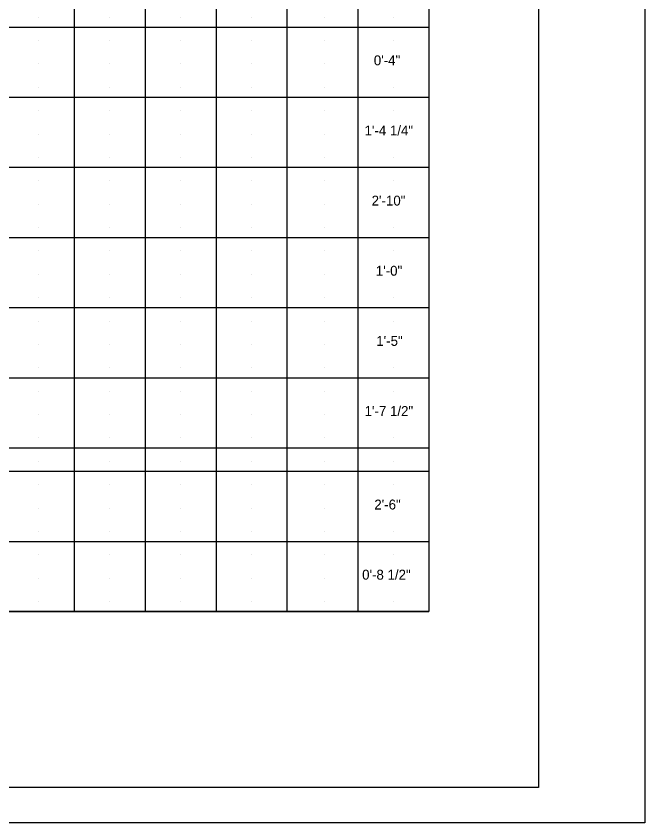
# Model space of a CAD drawing. Extents: x -31.1 to 2.9, y 8.5 to 31.4.
# Drawn here: x -6 to 2.87, y 8.48 to 19.87 of the extents above; entities that cross this region are included whole.
import ezdxf

# ---------------------------------------------------------------- set-up
doc = ezdxf.new("R2010")
doc.units = 0
doc.layers.add('BR_P_Gen_Text', color=7, linetype='Continuous')
doc.layers.add('SC_Scratch1', color=7, linetype='Continuous')

msp = doc.modelspace()

# ---------------------------------------------------------------- linework, layer by layer
at = {"layer": 'BR_P_Gen_Text'}
for p, q in [((-0.178, 29.627), (-0.178, 11.467)), ((-5.178, 28.577), (-5.178, 11.467)), ((-4.178, 28.577), (-4.178, 11.467)), ((-3.178, 28.577), (-3.178, 11.467)), ((-2.178, 28.577), (-2.178, 11.467)), ((-1.178, 28.577), (-1.178, 11.467)), ((-14.678, 19.717), (-0.178, 19.717)), ((-14.678, 18.727), (-0.178, 18.727)), ((-14.678, 17.737), (-0.178, 17.737)), ((-14.678, 16.747), (-0.178, 16.747)), ((-14.678, 15.757), (-0.178, 15.757)), ((-14.678, 14.767), (-0.178, 14.767)), ((-14.678, 13.777), (-0.178, 13.777)), ((-14.678, 13.447), (-0.178, 13.447)), ((-14.678, 12.457), (-0.178, 12.457)), ((-0.178, 11.467), (-14.678, 11.467)), ((-14.678, 11.467), (-0.178, 11.467)), ((-14.678, 11.467), (-0.178, 11.467))]:
    msp.add_line(p, q, dxfattribs=at)
for points in [[(-31.128, 30.484), (2.872, 30.484), (2.872, 8.484), (-31.128, 8.484)], [(-29.128, 29.984), (1.372, 29.984), (1.372, 8.984), (-29.128, 8.984)]]:
    msp.add_lwpolyline(points, close=True, dxfattribs=at)
at = {"layer": 'SC_Scratch1'}
for p, q in [((-5.677, 19.857), (-5.677, 19.857)), ((-5.677, 19.857), (-5.677, 19.857)), ((-4.678, 19.857), (-4.678, 19.857)), ((-4.678, 19.857), (-4.678, 19.857)), ((-3.678, 19.857), (-3.678, 19.857)), ((-2.678, 19.857), (-2.678, 19.857)), ((-1.655, 19.857), (-1.655, 19.857)), ((-0.678, 19.857), (-0.678, 19.857)), ((-5.677, 19.527), (-5.677, 19.527)), ((-5.677, 19.527), (-5.677, 19.527)), ((-4.678, 19.527), (-4.678, 19.527)), ((-4.678, 19.527), (-4.678, 19.527)), ((-3.678, 19.527), (-3.678, 19.527)), ((-2.678, 19.527), (-2.678, 19.527)), ((-1.655, 19.527), (-1.655, 19.527)), ((-0.678, 19.527), (-0.678, 19.527)), ((-5.677, 19.197), (-5.677, 19.197)), ((-5.677, 19.197), (-5.677, 19.197)), ((-4.678, 19.197), (-4.678, 19.197)), ((-4.678, 19.197), (-4.678, 19.197)), ((-3.678, 19.197), (-3.678, 19.197)), ((-2.678, 19.197), (-2.678, 19.197)), ((-1.655, 19.197), (-1.655, 19.197)), ((-0.678, 19.197), (-0.678, 19.197)), ((-5.677, 18.867), (-5.677, 18.867)), ((-5.677, 18.867), (-5.677, 18.867)), ((-4.678, 18.867), (-4.678, 18.867)), ((-4.678, 18.867), (-4.678, 18.867)), ((-3.678, 18.867), (-3.678, 18.867)), ((-2.678, 18.867), (-2.678, 18.867)), ((-1.655, 18.867), (-1.655, 18.867)), ((-0.678, 18.867), (-0.678, 18.867)), ((-5.677, 18.537), (-5.677, 18.537)), ((-5.677, 18.537), (-5.677, 18.537)), ((-4.678, 18.537), (-4.678, 18.537)), ((-4.678, 18.537), (-4.678, 18.537)), ((-3.678, 18.537), (-3.678, 18.537)), ((-2.678, 18.537), (-2.678, 18.537)), ((-1.655, 18.537), (-1.655, 18.537)), ((-0.678, 18.537), (-0.678, 18.537)), ((-5.677, 18.207), (-5.677, 18.207)), ((-5.677, 18.207), (-5.677, 18.207)), ((-4.678, 18.207), (-4.678, 18.207)), ((-4.678, 18.207), (-4.678, 18.207)), ((-3.678, 18.207), (-3.678, 18.207)), ((-2.678, 18.207), (-2.678, 18.207)), ((-1.655, 18.207), (-1.655, 18.207)), ((-0.678, 18.207), (-0.678, 18.207)), ((-5.677, 17.877), (-5.677, 17.877)), ((-5.677, 17.877), (-5.677, 17.877)), ((-4.678, 17.877), (-4.678, 17.877)), ((-4.678, 17.877), (-4.678, 17.877)), ((-3.678, 17.877), (-3.678, 17.877)), ((-2.678, 17.877), (-2.678, 17.877)), ((-1.655, 17.877), (-1.655, 17.877)), ((-0.678, 17.877), (-0.678, 17.877)), ((-5.677, 17.547), (-5.677, 17.547)), ((-5.677, 17.547), (-5.677, 17.547)), ((-4.678, 17.547), (-4.678, 17.547)), ((-4.678, 17.547), (-4.678, 17.547)), ((-3.678, 17.547), (-3.678, 17.547)), ((-2.678, 17.547), (-2.678, 17.547)), ((-1.655, 17.547), (-1.655, 17.547)), ((-0.678, 17.547), (-0.678, 17.547)), ((-5.677, 17.217), (-5.677, 17.217)), ((-5.677, 17.217), (-5.677, 17.217)), ((-4.678, 17.217), (-4.678, 17.217)), ((-4.678, 17.217), (-4.678, 17.217)), ((-3.678, 17.217), (-3.678, 17.217)), ((-2.678, 17.217), (-2.678, 17.217)), ((-1.655, 17.217), (-1.655, 17.217)), ((-0.678, 17.217), (-0.678, 17.217)), ((-5.677, 16.887), (-5.677, 16.887)), ((-5.677, 16.887), (-5.677, 16.887)), ((-4.678, 16.887), (-4.678, 16.887)), ((-4.678, 16.887), (-4.678, 16.887)), ((-3.678, 16.887), (-3.678, 16.887)), ((-2.678, 16.887), (-2.678, 16.887)), ((-1.655, 16.887), (-1.655, 16.887)), ((-0.678, 16.887), (-0.678, 16.887)), ((-5.677, 16.557), (-5.677, 16.557)), ((-5.677, 16.557), (-5.677, 16.557)), ((-4.678, 16.557), (-4.678, 16.557)), ((-4.678, 16.557), (-4.678, 16.557)), ((-3.678, 16.557), (-3.678, 16.557)), ((-2.678, 16.557), (-2.678, 16.557)), ((-1.655, 16.557), (-1.655, 16.557)), ((-0.678, 16.557), (-0.678, 16.557)), ((-5.677, 16.227), (-5.677, 16.227)), ((-5.677, 16.227), (-5.677, 16.227)), ((-4.678, 16.227), (-4.678, 16.227)), ((-4.678, 16.227), (-4.678, 16.227)), ((-3.678, 16.227), (-3.678, 16.227)), ((-2.678, 16.227), (-2.678, 16.227)), ((-1.655, 16.227), (-1.655, 16.227)), ((-0.678, 16.227), (-0.678, 16.227)), ((-5.677, 15.897), (-5.677, 15.897)), ((-5.677, 15.897), (-5.677, 15.897)), ((-4.678, 15.897), (-4.678, 15.897)), ((-4.678, 15.897), (-4.678, 15.897)), ((-3.678, 15.897), (-3.678, 15.897)), ((-2.678, 15.897), (-2.678, 15.897)), ((-1.655, 15.897), (-1.655, 15.897)), ((-0.678, 15.897), (-0.678, 15.897)), ((-5.677, 15.567), (-5.677, 15.567)), ((-5.677, 15.567), (-5.677, 15.567)), ((-4.678, 15.567), (-4.678, 15.567)), ((-4.678, 15.567), (-4.678, 15.567)), ((-3.678, 15.567), (-3.678, 15.567)), ((-2.678, 15.567), (-2.678, 15.567)), ((-1.655, 15.567), (-1.655, 15.567)), ((-0.678, 15.567), (-0.678, 15.567)), ((-5.677, 15.237), (-5.677, 15.237)), ((-5.677, 15.237), (-5.677, 15.237)), ((-4.678, 15.237), (-4.678, 15.237)), ((-4.678, 15.237), (-4.678, 15.237)), ((-3.678, 15.237), (-3.678, 15.237)), ((-2.678, 15.237), (-2.678, 15.237)), ((-1.655, 15.237), (-1.655, 15.237)), ((-0.678, 15.237), (-0.678, 15.237)), ((-5.677, 14.907), (-5.677, 14.907)), ((-5.677, 14.907), (-5.677, 14.907)), ((-4.678, 14.907), (-4.678, 14.907)), ((-4.678, 14.907), (-4.678, 14.907)), ((-3.678, 14.907), (-3.678, 14.907)), ((-2.678, 14.907), (-2.678, 14.907)), ((-1.655, 14.907), (-1.655, 14.907)), ((-0.678, 14.907), (-0.678, 14.907)), ((-5.677, 14.577), (-5.677, 14.577)), ((-5.677, 14.577), (-5.677, 14.577)), ((-4.678, 14.577), (-4.678, 14.577)), ((-4.678, 14.577), (-4.678, 14.577)), ((-3.678, 14.577), (-3.678, 14.577)), ((-2.678, 14.577), (-2.678, 14.577)), ((-1.655, 14.577), (-1.655, 14.577)), ((-0.678, 14.577), (-0.678, 14.577)), ((-5.677, 14.247), (-5.677, 14.247)), ((-5.677, 14.247), (-5.677, 14.247)), ((-4.678, 14.247), (-4.678, 14.247)), ((-4.678, 14.247), (-4.678, 14.247)), ((-3.678, 14.247), (-3.678, 14.247)), ((-2.678, 14.247), (-2.678, 14.247)), ((-1.655, 14.247), (-1.655, 14.247)), ((-0.678, 14.247), (-0.678, 14.247)), ((-5.677, 13.917), (-5.677, 13.917)), ((-5.677, 13.917), (-5.677, 13.917)), ((-4.678, 13.917), (-4.678, 13.917)), ((-4.678, 13.917), (-4.678, 13.917)), ((-3.678, 13.917), (-3.678, 13.917)), ((-2.678, 13.917), (-2.678, 13.917)), ((-1.655, 13.917), (-1.655, 13.917)), ((-0.678, 13.917), (-0.678, 13.917)), ((-5.677, 13.587), (-5.677, 13.587)), ((-5.677, 13.587), (-5.677, 13.587)), ((-4.678, 13.587), (-4.678, 13.587)), ((-4.678, 13.587), (-4.678, 13.587)), ((-3.678, 13.587), (-3.678, 13.587)), ((-2.678, 13.587), (-2.678, 13.587)), ((-1.655, 13.587), (-1.655, 13.587)), ((-0.678, 13.587), (-0.678, 13.587)), ((-5.677, 13.257), (-5.677, 13.257)), ((-5.677, 13.257), (-5.677, 13.257)), ((-4.678, 13.257), (-4.678, 13.257)), ((-4.678, 13.257), (-4.678, 13.257)), ((-3.678, 13.257), (-3.678, 13.257)), ((-2.678, 13.257), (-2.678, 13.257)), ((-1.655, 13.257), (-1.655, 13.257)), ((-0.678, 13.257), (-0.678, 13.257)), ((-5.677, 12.927), (-5.677, 12.927)), ((-5.677, 12.927), (-5.677, 12.927)), ((-4.678, 12.927), (-4.678, 12.927)), ((-4.678, 12.927), (-4.678, 12.927)), ((-3.678, 12.927), (-3.678, 12.927)), ((-2.678, 12.927), (-2.678, 12.927)), ((-1.655, 12.927), (-1.655, 12.927)), ((-0.678, 12.927), (-0.678, 12.927)), ((-5.677, 12.597), (-5.677, 12.597)), ((-5.677, 12.597), (-5.677, 12.597)), ((-4.678, 12.597), (-4.678, 12.597)), ((-4.678, 12.597), (-4.678, 12.597)), ((-3.678, 12.597), (-3.678, 12.597)), ((-2.678, 12.597), (-2.678, 12.597)), ((-1.655, 12.597), (-1.655, 12.597)), ((-0.678, 12.597), (-0.678, 12.597)), ((-5.677, 12.267), (-5.677, 12.267)), ((-5.677, 12.267), (-5.677, 12.267)), ((-4.678, 12.267), (-4.678, 12.267)), ((-4.678, 12.267), (-4.678, 12.267)), ((-3.678, 12.267), (-3.678, 12.267)), ((-2.678, 12.267), (-2.678, 12.267)), ((-1.655, 12.267), (-1.655, 12.267)), ((-0.678, 12.267), (-0.678, 12.267)), ((-5.677, 11.937), (-5.677, 11.937)), ((-5.677, 11.937), (-5.677, 11.937)), ((-4.678, 11.937), (-4.678, 11.937)), ((-4.678, 11.937), (-4.678, 11.937)), ((-3.678, 11.937), (-3.678, 11.937)), ((-2.678, 11.937), (-2.678, 11.937)), ((-1.655, 11.937), (-1.655, 11.937)), ((-0.678, 11.937), (-0.678, 11.937)), ((-5.677, 11.607), (-5.677, 11.607)), ((-5.677, 11.607), (-5.677, 11.607)), ((-4.678, 11.607), (-4.678, 11.607)), ((-4.678, 11.607), (-4.678, 11.607)), ((-3.678, 11.607), (-3.678, 11.607)), ((-2.678, 11.607), (-2.678, 11.607)), ((-1.655, 11.607), (-1.655, 11.607)), ((-0.678, 11.607), (-0.678, 11.607))]:
    msp.add_line(p, q, dxfattribs=at)

# ---------------------------------------------------------------- texts
at = {"layer": 'BR_P_Gen_Text'}
for s, p in [('0\'-4"', (-0.952, 19.177)), ('1\'-4 1/4"', (-1.083, 18.187)), ('2\'-10"', (-0.983, 17.197)), ('1\'-0"', (-0.924, 16.207)), ('1\'-5"', (-0.917, 15.217)), ('1\'-7 1/2"', (-1.082, 14.227)), ('2\'-6"', (-0.945, 12.907)), ('0\'-8 1/2"', (-1.117, 11.917))]:
    msp.add_text(s, height=0.14, dxfattribs=at).set_placement(p)

doc.saveas('drawing.dxf')
